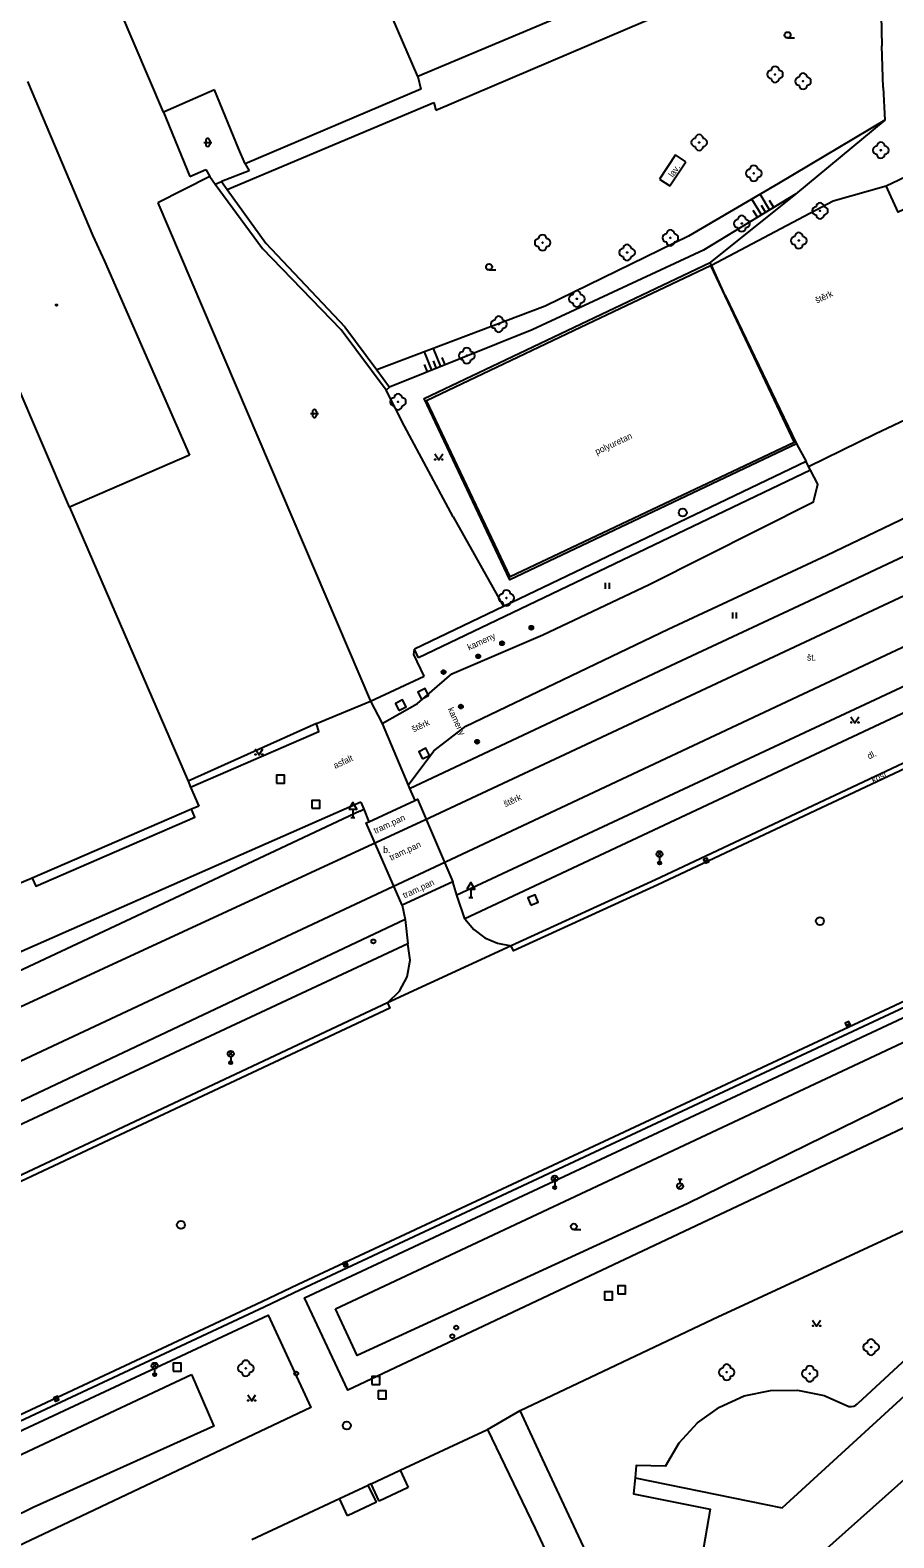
# Model space of a CAD drawing. Extents: x -599770 to -598493, y -1162076 to -1159209.
# Drawn here: x -599489.7 to -599435.5, y -1161324.7 to -1161229.9 of the extents above; entities that cross this region are included whole.
import ezdxf

# ---------------------------------------------------------------- set-up
doc = ezdxf.new("R2010")
doc.units = 0
doc.layers.add('Podklad', color=7, linetype='Continuous')

msp = doc.modelspace()

# ---------------------------------------------------------------- linework, layer by layer
at = {"layer": 'Podklad'}
for p, q in [((-599442.13, -1161230.398), (-599441.692, -1161230.398)), ((-599478.833, -1161236.968), (-599478.333, -1161236.968)), ((-599478.708, -1161236.843), (-599478.708, -1161237.093)), ((-599478.458, -1161236.843), (-599478.458, -1161237.093)), ((-599460.9, -1161244.988), (-599460.462, -1161244.988)), ((-599472.123, -1161254.018), (-599471.623, -1161254.018)), ((-599471.998, -1161253.893), (-599471.998, -1161254.143)), ((-599471.748, -1161253.893), (-599471.748, -1161254.143)), ((-599453.582, -1161265.037), (-599453.582, -1161264.662)), ((-599453.332, -1161265.037), (-599453.332, -1161264.662)), ((-599445.582, -1161266.907), (-599445.582, -1161266.532)), ((-599445.332, -1161266.907), (-599445.332, -1161266.532)), ((-599469.46, -1161278.911), (-599469.46, -1161279.42)), ((-599469.585, -1161279.42), (-599469.335, -1161279.42)), ((-599450.312, -1161281.86), (-599450.047, -1161281.595)), ((-599450.312, -1161281.595), (-599450.047, -1161281.86)), ((-599450.18, -1161281.915), (-599450.18, -1161282.29)), ((-599447.366, -1161282.186), (-599447.134, -1161282.094)), ((-599462.05, -1161283.941), (-599462.05, -1161284.45)), ((-599462.175, -1161284.45), (-599461.925, -1161284.45)), ((-599438.455, -1161292.479), (-599438.225, -1161292.381)), ((-599477.273, -1161294.42), (-599477.008, -1161294.155)), ((-599477.273, -1161294.155), (-599477.008, -1161294.42)), ((-599477.14, -1161294.475), (-599477.14, -1161294.85)), ((-599456.902, -1161302.27), (-599456.637, -1161302.005)), ((-599456.902, -1161302.005), (-599456.637, -1161302.27)), ((-599456.77, -1161302.325), (-599456.77, -1161302.7)), ((-599449.019, -1161302.746), (-599448.754, -1161302.481)), ((-599449.015, -1161302.172), (-599448.765, -1161302.172)), ((-599448.89, -1161302.422), (-599448.89, -1161302.172)), ((-599455.57, -1161305.348), (-599455.133, -1161305.348)), ((-599470.045, -1161307.569), (-599469.815, -1161307.471)), ((-599482.053, -1161314.04), (-599481.788, -1161313.775)), ((-599482.053, -1161313.775), (-599481.788, -1161314.04)), ((-599481.92, -1161314.095), (-599481.92, -1161314.47)), ((-599488.215, -1161316.039), (-599487.985, -1161315.941))]:
    msp.add_line(p, q, dxfattribs=at)
for points in [[(-599465.37, -1161232.83), (-599473.25, -1161214.59)], [(-599436.49, -1161222.15), (-599436.26, -1161228.02), (-599436.21, -1161230.9)], [(-599429.92, -1161238.92), (-599435.17, -1161241.36), (-599435.94, -1161239.69), (-599417.82, -1161231.11), (-599400.21, -1161222.81)], [(-599481.37, -1161235.07), (-599485.06, -1161226.41)], [(-599453.89, -1161227.98), (-599465.37, -1161232.83)], [(-599464.24, -1161234.93), (-599449.94, -1161228.84)], [(-599436.13, -1161233.51), (-599436.21, -1161230.9)], [(-599465.37, -1161232.83), (-599465.18, -1161233.61)], [(-599489.92, -1161233.14), (-599485.81, -1161242.85)], [(-599478.16, -1161233.65), (-599481.08, -1161234.94)], [(-599476.62, -1161237.39), (-599478.16, -1161233.65)], [(-599465.18, -1161233.61), (-599476.24, -1161238.32)], [(-599436.13, -1161233.51), (-599436.02, -1161235.57), (-599441.64, -1161240.22), (-599446.99, -1161244.52)], [(-599477.36, -1161239.93), (-599464.36, -1161234.45)], [(-599464.36, -1161234.45), (-599464.24, -1161234.93)], [(-599481.08, -1161234.94), (-599481.37, -1161235.07)], [(-599481.37, -1161235.07), (-599479.71, -1161239.11)], [(-599436.02, -1161235.57), (-599442.7, -1161239.55), (-599448.37, -1161242.87), (-599457.37, -1161247.26), (-599467.95, -1161251.28)], [(-599476.24, -1161238.32), (-599476.62, -1161237.39)], [(-599476.24, -1161238.32), (-599475.98, -1161238.75)], [(-599449.18, -1161237.75), (-599450.19, -1161239.27)], [(-599449.54, -1161239.69), (-599448.52, -1161238.19)], [(-599448.52, -1161238.19), (-599449.18, -1161237.75)], [(-599518.64, -1161304.39), (-599464.62, -1161279.43), (-599424.64, -1161260.7), (-599378.29, -1161238.9)], [(-599478.46, -1161239.11), (-599481.71, -1161240.77)], [(-599479.71, -1161239.11), (-599478.71, -1161238.67)], [(-599478.71, -1161238.67), (-599478.46, -1161239.11)], [(-599478.46, -1161239.11), (-599478.11, -1161239.59)], [(-599478.11, -1161239.59), (-599477.71, -1161239.43)], [(-599475.98, -1161238.75), (-599477.71, -1161239.43)], [(-599477.71, -1161239.43), (-599477.36, -1161239.93)], [(-599450.19, -1161239.27), (-599449.54, -1161239.69)], [(-599478.11, -1161239.59), (-599475.14, -1161243.63)], [(-599477.36, -1161239.93), (-599474.93, -1161243.3)], [(-599441.64, -1161240.22), (-599447.42, -1161243.74), (-599458.19, -1161248.76), (-599467.15, -1161252.36)], [(-599465.89, -1161277.6), (-599449.11, -1161269.69), (-599440.78, -1161265.8), (-599436.96, -1161264), (-599426.82, -1161259.22), (-599404.81, -1161249), (-599386.02, -1161240.1)], [(-599446.92, -1161244.68), (-599439.27, -1161240.63), (-599435.94, -1161239.69)], [(-599443.26, -1161241.21), (-599443.85, -1161240.23)], [(-599481.71, -1161240.77), (-599468.36, -1161272.1)], [(-599443.77, -1161241.52), (-599444.37, -1161240.53)], [(-599444.03, -1161241.67), (-599444.29, -1161241.25)], [(-599443.51, -1161241.36), (-599443.77, -1161240.93)], [(-599443, -1161241.05), (-599443.26, -1161240.62)], [(-599376.74, -1161241.49), (-599423.17, -1161263.23), (-599463.27, -1161282.06), (-599517.44, -1161307.45)], [(-599485.81, -1161242.85), (-599485.08, -1161244.43)], [(-599470.19, -1161248.75), (-599475.14, -1161243.63)], [(-599474.93, -1161243.3), (-599469.97, -1161248.56)], [(-599485.08, -1161244.43), (-599479.72, -1161256.63)], [(-599446.06, -1161246.59), (-599441.58, -1161255.92), (-599459.6, -1161264.47), (-599464.97, -1161253.08), (-599446.99, -1161244.52)], [(-599446.97, -1161244.71), (-599441.71, -1161255.83), (-599459.58, -1161264.29), (-599464.84, -1161253.19), (-599455.55, -1161248.78), (-599446.97, -1161244.71)], [(-599374.58, -1161244.63), (-599380.48, -1161247.39), (-599382.83, -1161248.49), (-599418.38, -1161265.13), (-599462.42, -1161285.81)], [(-599446.92, -1161244.68), (-599446.99, -1161244.52)], [(-599446.97, -1161244.71), (-599446.92, -1161244.68)], [(-599446.06, -1161246.59), (-599446.92, -1161244.68)], [(-599383.12, -1161246.8), (-599419.17, -1161263.87), (-599462.93, -1161284.32)], [(-599342.09, -1161247.58), (-599378.65, -1161264.68), (-599391.36, -1161270.66), (-599400.18, -1161274.79), (-599421.28, -1161284.67), (-599472.9, -1161308.81), (-599475.18, -1161309.9), (-599507.88, -1161325.2), (-599523.58, -1161330.77)], [(-599487.28, -1161259.9), (-599492.52, -1161247.7)], [(-599373.17, -1161247.12), (-599388.05, -1161254.26), (-599417.2, -1161267.7), (-599450.43, -1161283.35), (-599459.51, -1161287.5)], [(-599373.02, -1161247.44), (-599387.9, -1161254.58), (-599417.05, -1161268.02), (-599450.28, -1161283.67), (-599459.36, -1161287.82), (-599459.51, -1161287.5)], [(-599467.15, -1161252.36), (-599467.37, -1161252.55), (-599470.19, -1161248.75)], [(-599467.15, -1161252.36), (-599467.37, -1161252.55), (-599470.19, -1161248.75)], [(-599469.97, -1161248.56), (-599467.95, -1161251.28), (-599467.15, -1161252.36)], [(-599464.49, -1161251.29), (-599464.95, -1161250.14)], [(-599463.93, -1161251.07), (-599464.39, -1161249.93)], [(-599464.21, -1161251.18), (-599464.39, -1161250.71)], [(-599463.65, -1161250.95), (-599463.84, -1161250.49)], [(-599464.76, -1161251.4), (-599464.95, -1161250.94)], [(-599463.15, -1161260.52), (-599466.21, -1161254.82), (-599467.37, -1161252.55)], [(-599436.63, -1161255.3), (-599434.31, -1161254.21)], [(-599440.81, -1161257.34), (-599436.63, -1161255.3)], [(-599441.58, -1161255.92), (-599440.96, -1161257.03)], [(-599479.72, -1161256.63), (-599487.28, -1161259.9)], [(-599440.96, -1161257.03), (-599459.99, -1161266.15), (-599465.59, -1161268.84)], [(-599464.31, -1161256.555), (-599464.06, -1161256.93), (-599463.81, -1161256.555)], [(-599440.7, -1161257.58), (-599440.81, -1161257.34), (-599440.96, -1161257.03)], [(-599439.66, -1161262.93), (-599427.38, -1161257.04)], [(-599467.62, -1161273.52), (-599465.4, -1161272.25), (-599463.24, -1161270.39), (-599457.51, -1161267.94), (-599450.84, -1161264.77), (-599440.51, -1161259.57), (-599440.22, -1161258.46), (-599440.7, -1161257.58)], [(-599440.7, -1161257.58), (-599465.33, -1161269.38)], [(-599487.28, -1161259.9), (-599479.82, -1161277.15)], [(-599463.15, -1161260.52), (-599459.99, -1161266.15)], [(-599449.64, -1161267.59), (-599439.66, -1161262.93)], [(-599465.98, -1161277.39), (-599464.37, -1161275.24), (-599462.35, -1161273.69), (-599449.64, -1161267.59)], [(-599465.62, -1161269.18), (-599465.59, -1161268.84)], [(-599465.33, -1161269.38), (-599465.59, -1161268.84)], [(-599464.98, -1161270.53), (-599465.62, -1161269.18)], [(-599468.36, -1161272.1), (-599464.98, -1161270.53)], [(-599468.36, -1161272.1), (-599464.98, -1161270.53)], [(-599471.74, -1161273.51), (-599468.36, -1161272.1)], [(-599468.36, -1161272.1), (-599467.62, -1161273.52)], [(-599471.74, -1161273.51), (-599479.82, -1161277.15)], [(-599479.66, -1161277.52), (-599471.6, -1161274.01), (-599471.74, -1161273.51)], [(-599467.62, -1161273.52), (-599465.98, -1161277.39)], [(-599438.15, -1161273.095), (-599437.9, -1161273.47), (-599437.65, -1161273.095)], [(-599400.03, -1161275.11), (-599421.13, -1161284.99), (-599472.75, -1161309.13), (-599475.03, -1161310.22), (-599507.75, -1161325.52), (-599523.42, -1161331.08)], [(-599475.61, -1161275.115), (-599475.36, -1161275.49), (-599475.11, -1161275.115)], [(-599479.82, -1161277.15), (-599479.66, -1161277.52)], [(-599465.98, -1161277.39), (-599465.89, -1161277.6)], [(-599479.66, -1161277.52), (-599479.15, -1161278.71)], [(-599468.46, -1161279.69), (-599465.57, -1161278.36)], [(-599465.89, -1161277.6), (-599465.57, -1161278.36)], [(-599465.57, -1161278.36), (-599465.4, -1161278.28), (-599463.18, -1161283.47)], [(-599469.02, -1161279.02), (-599480.33, -1161284.35), (-599500.02, -1161293.57), (-599520.92, -1161302.99), (-599525.68, -1161304.53), (-599531.36, -1161305.67), (-599537.89, -1161306.54)], [(-599468.96, -1161278.46), (-599492.07, -1161288.63), (-599526.59, -1161304)], [(-599479.61, -1161278.91), (-599489.61, -1161283.24)], [(-599489.61, -1161283.24), (-599489.39, -1161283.75), (-599479.39, -1161279.41), (-599479.61, -1161278.91)], [(-599479.15, -1161278.71), (-599479.61, -1161278.91)], [(-599469.02, -1161279.02), (-599468.78, -1161278.91)], [(-599468.96, -1161278.46), (-599468.78, -1161278.91)], [(-599468.78, -1161278.91), (-599468.46, -1161279.69)], [(-599466.35, -1161284.95), (-599468.63, -1161279.77), (-599468.46, -1161279.69)], [(-599489.61, -1161283.24), (-599490.56, -1161283.65)], [(-599463.18, -1161283.47), (-599466.35, -1161284.95)], [(-599462.93, -1161284.32), (-599463.18, -1161283.47)], [(-599466.35, -1161284.95), (-599466.17, -1161285.85)], [(-599462.42, -1161285.81), (-599462.93, -1161284.32)], [(-599466.17, -1161285.85), (-599513.93, -1161308.42)], [(-599466.17, -1161285.85), (-599466, -1161287.38)], [(-599462.42, -1161285.81), (-599461.86, -1161286.48), (-599461.16, -1161287), (-599460.37, -1161287.34), (-599459.51, -1161287.5)], [(-599466, -1161287.38), (-599518.56, -1161311.92)], [(-599467.28, -1161291.09), (-599466.53, -1161290.36), (-599466.05, -1161289.44), (-599465.86, -1161288.41), (-599466, -1161287.38)], [(-599459.51, -1161287.5), (-599467.28, -1161291.09)], [(-599422.64, -1161293.21), (-599469.78, -1161315.45), (-599472.51, -1161309.63), (-599426.07, -1161287.9)], [(-599467.28, -1161291.09), (-599501.57, -1161307.2), (-599518.81, -1161315.03)], [(-599467.28, -1161291.09), (-599467.13, -1161291.41), (-599501.42, -1161307.52), (-599518.69, -1161315.36)], [(-599470.55, -1161310.33), (-599434.58, -1161293.43)], [(-599434.58, -1161293.43), (-599433.45, -1161296.36), (-599448.44, -1161303.73), (-599469.19, -1161313.27), (-599470.55, -1161310.33)], [(-599449.8, -1161320.23), (-599451.64, -1161320.19), (-599451.71, -1161320.96), (-599451.81, -1161321.96), (-599447, -1161322.94), (-599448.05, -1161329.01), (-599443.52, -1161329.79), (-599443.33, -1161328.67), (-599432.69, -1161319.18), (-599434.31, -1161317.41), (-599422.58, -1161306.67), (-599425.22, -1161301.03), (-599424.86, -1161300.88)], [(-599444.98, -1161337.11), (-599446.43, -1161335.49), (-599449.52, -1161336.93), (-599457.53, -1161319.77), (-599458.95, -1161316.72), (-599446.48, -1161310.82), (-599445.16, -1161310.2), (-599426.68, -1161301.63), (-599425.18, -1161304.7), (-599437.71, -1161316.28)], [(-599451.71, -1161320.96), (-599442.47, -1161322.85), (-599424.59, -1161306.47)], [(-599520.4, -1161330.82), (-599507.54, -1161326.03), (-599474.79, -1161310.72), (-599472.11, -1161316.53), (-599506.92, -1161333.03), (-599509.39, -1161334.05), (-599518.43, -1161337.01)], [(-599440.56, -1161311.045), (-599440.31, -1161311.42), (-599440.06, -1161311.045)], [(-599505.34, -1161326.54), (-599479.6, -1161314.45)], [(-599479.6, -1161314.45), (-599478.19, -1161317.7), (-599489.56, -1161322.83), (-599503.65, -1161329.77), (-599505.34, -1161326.54)], [(-599476.07, -1161315.745), (-599475.82, -1161316.12), (-599475.57, -1161315.745)], [(-599449.8, -1161320.23), (-599448.94, -1161318.76), (-599447.8, -1161317.5), (-599446.42, -1161316.51), (-599444.87, -1161315.81), (-599443.2, -1161315.46), (-599441.51, -1161315.45), (-599439.84, -1161315.79), (-599438.28, -1161316.47)], [(-599438.28, -1161316.47), (-599438.12, -1161316.48), (-599437.97, -1161316.45), (-599437.83, -1161316.38), (-599437.71, -1161316.28)], [(-599460.99, -1161317.91), (-599458.95, -1161316.72)], [(-599466.49, -1161320.48), (-599460.99, -1161317.91)], [(-599460.99, -1161317.91), (-599457.99, -1161324.15)], [(-599468.31, -1161321.33), (-599466.49, -1161320.48)], [(-599466.49, -1161320.48), (-599465.99, -1161321.57)], [(-599470.3, -1161322.26), (-599468.49, -1161321.42)], [(-599468.31, -1161321.33), (-599468.49, -1161321.42)], [(-599467.98, -1161322.5), (-599468.49, -1161321.42)], [(-599467.8, -1161322.42), (-599468.31, -1161321.33)], [(-599465.99, -1161321.57), (-599467.8, -1161322.42)], [(-599475.81, -1161324.84), (-599470.3, -1161322.26)], [(-599469.79, -1161323.35), (-599470.3, -1161322.26)], [(-599467.98, -1161322.5), (-599469.79, -1161323.35)], [(-599457.99, -1161324.15), (-599456.47, -1161327.42)]]:
    msp.add_lwpolyline(points, dxfattribs=at)
for points in [[(-599465.142, -1161271.985), (-599464.695, -1161271.762), (-599464.918, -1161271.315), (-599465.365, -1161271.538)], [(-599466.562, -1161272.695), (-599466.115, -1161272.472), (-599466.338, -1161272.025), (-599466.785, -1161272.248)], [(-599465.092, -1161275.745), (-599464.645, -1161275.522), (-599464.868, -1161275.075), (-599465.315, -1161275.298)], [(-599474.25, -1161277.26), (-599473.75, -1161277.26), (-599473.75, -1161276.76), (-599474.25, -1161276.76)], [(-599472.03, -1161278.85), (-599471.53, -1161278.85), (-599471.53, -1161278.35), (-599472.03, -1161278.35)], [(-599469.71, -1161278.911), (-599469.21, -1161278.911), (-599469.46, -1161278.478)], [(-599447.32, -1161282.302), (-599447.088, -1161282.21), (-599447.18, -1161281.978), (-599447.412, -1161282.07)], [(-599462.3, -1161283.941), (-599461.8, -1161283.941), (-599462.05, -1161283.508)], [(-599458.272, -1161284.938), (-599457.812, -1161284.742), (-599458.008, -1161284.282), (-599458.468, -1161284.478)], [(-599438.406, -1161292.594), (-599438.176, -1161292.496), (-599438.274, -1161292.266), (-599438.504, -1161292.364)], [(-599469.996, -1161307.684), (-599469.766, -1161307.586), (-599469.864, -1161307.356), (-599470.094, -1161307.454)], [(-599453.64, -1161309.76), (-599453.14, -1161309.76), (-599453.14, -1161309.26), (-599453.64, -1161309.26)], [(-599452.81, -1161309.38), (-599452.31, -1161309.38), (-599452.31, -1161308.88), (-599452.81, -1161308.88)], [(-599480.76, -1161314.25), (-599480.26, -1161314.25), (-599480.26, -1161313.75), (-599480.76, -1161313.75)], [(-599468.27, -1161315.08), (-599467.77, -1161315.08), (-599467.77, -1161314.58), (-599468.27, -1161314.58)], [(-599488.166, -1161316.154), (-599487.936, -1161316.056), (-599488.034, -1161315.826), (-599488.264, -1161315.924)], [(-599467.86, -1161315.99), (-599467.36, -1161315.99), (-599467.36, -1161315.49), (-599467.86, -1161315.49)]]:
    msp.add_lwpolyline(points, close=True, dxfattribs=at)
for centre, radius in [((-599442.13, -1161230.21), 0.188), ((-599442.92, -1161232.69), 0.025), ((-599441.16, -1161233.12), 0.025), ((-599447.69, -1161236.97), 0.025), ((-599436.27, -1161237.46), 0.025), ((-599444.26, -1161238.91), 0.025), ((-599440.09, -1161241.27), 0.025), ((-599445.01, -1161242.07), 0.025), ((-599457.53, -1161243.27), 0.025), ((-599449.5, -1161242.97), 0.025), ((-599441.43, -1161243.14), 0.025), ((-599452.22, -1161243.89), 0.025), ((-599460.9, -1161244.8), 0.188), ((-599455.38, -1161246.81), 0.025), ((-599488.09, -1161247.2), 0.045), ((-599488.09, -1161247.2), 0.0199), ((-599460.29, -1161248.4), 0.025), ((-599462.3, -1161250.38), 0.025), ((-599466.62, -1161253.28), 0.025), ((-599464.285, -1161256.905), 0.025), ((-599463.835, -1161256.905), 0.025), ((-599448.72, -1161260.25), 0.25), ((-599459.81, -1161265.62), 0.025), ((-599458.24, -1161267.49), 0.125), ((-599458.24, -1161267.49), 0.0152), ((-599460.08, -1161268.47), 0.125), ((-599460.08, -1161268.47), 0.0152), ((-599461.58, -1161269.29), 0.125), ((-599461.58, -1161269.29), 0.0152), ((-599463.76, -1161270.28), 0.125), ((-599463.76, -1161270.28), 0.0152), ((-599462.67, -1161272.45), 0.125), ((-599462.67, -1161272.45), 0.0152), ((-599438.125, -1161273.445), 0.025), ((-599437.675, -1161273.445), 0.025), ((-599461.65, -1161274.66), 0.125), ((-599475.585, -1161275.465), 0.025), ((-599475.135, -1161275.465), 0.025), ((-599461.65, -1161274.66), 0.0152), ((-599450.18, -1161281.727), 0.188), ((-599450.18, -1161282.29), 0.1), ((-599450.18, -1161282.29), 0.0723), ((-599450.18, -1161282.29), 0.0438), ((-599440.1, -1161285.94), 0.25), ((-599468.17, -1161287.22), 0.125), ((-599477.14, -1161294.288), 0.188), ((-599477.14, -1161294.85), 0.1), ((-599477.14, -1161294.85), 0.0723), ((-599477.14, -1161294.85), 0.0438), ((-599456.77, -1161302.137), 0.188), ((-599456.77, -1161302.7), 0.1), ((-599456.77, -1161302.7), 0.0723), ((-599456.77, -1161302.7), 0.0438), ((-599448.89, -1161302.61), 0.188), ((-599480.27, -1161305.05), 0.25), ((-599455.57, -1161305.16), 0.188), ((-599462.96, -1161311.51), 0.125), ((-599440.535, -1161311.395), 0.025), ((-599440.085, -1161311.395), 0.025), ((-599463.21, -1161312.05), 0.125), ((-599436.88, -1161312.74), 0.025), ((-599481.92, -1161313.907), 0.188), ((-599481.92, -1161314.47), 0.1), ((-599476.19, -1161314.07), 0.025), ((-599473.02, -1161314.4), 0.125), ((-599445.96, -1161314.32), 0.025), ((-599440.74, -1161314.41), 0.025), ((-599481.92, -1161314.47), 0.0723), ((-599481.92, -1161314.47), 0.0438), ((-599476.045, -1161316.095), 0.025), ((-599475.595, -1161316.095), 0.025), ((-599469.84, -1161317.67), 0.25)]:
    msp.add_circle(centre, radius, dxfattribs=at)
for centre, radius, start, end in [((-599443.17, -1161232.69), 0.25, 90, 270), ((-599442.92, -1161232.44), 0.25, 0, 180), ((-599442.67, -1161232.69), 0.25, 270, 90), ((-599441.16, -1161232.87), 0.25, 0, 180), ((-599442.92, -1161232.94), 0.25, 180, 0), ((-599441.41, -1161233.12), 0.25, 90, 270), ((-599441.16, -1161233.37), 0.25, 180, 0), ((-599440.91, -1161233.12), 0.25, 270, 90), ((-599447.69, -1161236.72), 0.25, 0, 180), ((-599478.583, -1161236.843), 0.125, 0, 180), ((-599478.583, -1161237.093), 0.125, 180, 0), ((-599447.94, -1161236.97), 0.25, 90, 270), ((-599447.69, -1161237.22), 0.25, 180, 0), ((-599447.44, -1161236.97), 0.25, 270, 90), ((-599436.52, -1161237.46), 0.25, 90, 270), ((-599436.27, -1161237.21), 0.25, 0, 180), ((-599436.02, -1161237.46), 0.25, 270, 90), ((-599444.26, -1161238.66), 0.25, 0, 180), ((-599436.27, -1161237.71), 0.25, 180, 0), ((-599444.51, -1161238.91), 0.25, 90, 270), ((-599444.26, -1161239.16), 0.25, 180, 0), ((-599444.01, -1161238.91), 0.25, 270, 90), ((-599440.34, -1161241.27), 0.25, 90, 270), ((-599440.09, -1161241.02), 0.25, 0, 180), ((-599439.84, -1161241.27), 0.25, 270, 90), ((-599445.26, -1161242.07), 0.25, 90, 270), ((-599445.01, -1161241.82), 0.25, 0, 180), ((-599445.01, -1161242.32), 0.25, 180, 0), ((-599444.76, -1161242.07), 0.25, 270, 90), ((-599440.09, -1161241.52), 0.25, 180, 0), ((-599457.78, -1161243.27), 0.25, 90, 270), ((-599457.53, -1161243.02), 0.25, 0, 180), ((-599457.28, -1161243.27), 0.25, 270, 90), ((-599449.75, -1161242.97), 0.25, 90, 270), ((-599449.5, -1161242.72), 0.25, 0, 180), ((-599449.5, -1161243.22), 0.25, 180, 0), ((-599449.25, -1161242.97), 0.25, 270, 90), ((-599441.68, -1161243.14), 0.25, 90, 270), ((-599441.43, -1161242.89), 0.25, 0, 180), ((-599441.18, -1161243.14), 0.25, 270, 90), ((-599457.53, -1161243.52), 0.25, 180, 0), ((-599452.47, -1161243.89), 0.25, 90, 270), ((-599452.22, -1161243.64), 0.25, 0, 180), ((-599452.22, -1161244.14), 0.25, 180, 0), ((-599451.97, -1161243.89), 0.25, 270, 90), ((-599441.43, -1161243.39), 0.25, 180, 0), ((-599455.63, -1161246.81), 0.25, 90, 270), ((-599455.38, -1161246.56), 0.25, 0, 180), ((-599455.38, -1161247.06), 0.25, 180, 0), ((-599455.13, -1161246.81), 0.25, 270, 90), ((-599460.29, -1161248.15), 0.25, 0, 180), ((-599460.54, -1161248.4), 0.25, 90, 270), ((-599460.29, -1161248.65), 0.25, 180, 0), ((-599460.04, -1161248.4), 0.25, 270, 90), ((-599462.3, -1161250.13), 0.25, 0, 180), ((-599462.55, -1161250.38), 0.25, 90, 270), ((-599462.3, -1161250.63), 0.25, 180, 0), ((-599462.05, -1161250.38), 0.25, 270, 90), ((-599466.87, -1161253.28), 0.25, 90, 270), ((-599466.62, -1161253.03), 0.25, 0, 180), ((-599466.62, -1161253.53), 0.25, 180, 0), ((-599466.37, -1161253.28), 0.25, 270, 90), ((-599471.873, -1161253.893), 0.125, 0, 180), ((-599471.873, -1161254.143), 0.125, 180, 0), ((-599460.06, -1161265.62), 0.25, 90, 270), ((-599459.81, -1161265.37), 0.25, 0, 180), ((-599459.81, -1161265.87), 0.25, 180, 0), ((-599459.56, -1161265.62), 0.25, 270, 90), ((-599437.13, -1161312.74), 0.25, 90, 270), ((-599436.88, -1161312.49), 0.25, 0, 180), ((-599436.63, -1161312.74), 0.25, 270, 90), ((-599436.88, -1161312.99), 0.25, 180, 0), ((-599476.44, -1161314.07), 0.25, 90, 270), ((-599476.19, -1161313.82), 0.25, 0, 180), ((-599476.19, -1161314.32), 0.25, 180, 0), ((-599475.94, -1161314.07), 0.25, 270, 90), ((-599446.21, -1161314.32), 0.25, 90, 270), ((-599445.96, -1161314.07), 0.25, 0, 180), ((-599445.71, -1161314.32), 0.25, 270, 90), ((-599440.99, -1161314.41), 0.25, 90, 270), ((-599440.74, -1161314.16), 0.25, 0, 180), ((-599440.49, -1161314.41), 0.25, 270, 90), ((-599445.96, -1161314.57), 0.25, 180, 0), ((-599440.74, -1161314.66), 0.25, 180, 0)]:
    msp.add_arc(centre, radius, start, end, dxfattribs=at)

# ---------------------------------------------------------------- texts
for s, rotation, p in [('lav.', 55.7843, (-599449.33, -1161239.2)), ('štěrk', 25, (-599440.29, -1161247.11)), ('polyuretan', 25, (-599454.12, -1161256.62)), ('kameny', 25, (-599462.15, -1161268.93)), ('kameny', 295, (-599463.51, -1161272.61)), ('štěrk', 25, (-599465.64, -1161274.08)), ('asfalt', 25, (-599470.57, -1161276.37)), ('dl.', 25.18, (-599437.01, -1161275.78)), ('kost.', 25.08, (-599436.75, -1161277.27)), ('štěrk', 25, (-599459.87, -1161278.78)), ('tram.pan', 25, (-599468.04, -1161280.46)), ('tram.pan', 25, (-599467.05, -1161282.15)), ('tram.pan', 25, (-599466.21, -1161284.53))]:
    msp.add_text(s, height=0.4, rotation=rotation, dxfattribs=at).set_placement(p)
for s, p in [('št.', (-599440.91, -1161269.56)), ('b.', (-599467.55, -1161281.65))]:
    msp.add_text(s, height=0.4, dxfattribs=at).set_placement(p)

doc.saveas('drawing.dxf')
